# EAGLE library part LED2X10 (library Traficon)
PIN HEADER
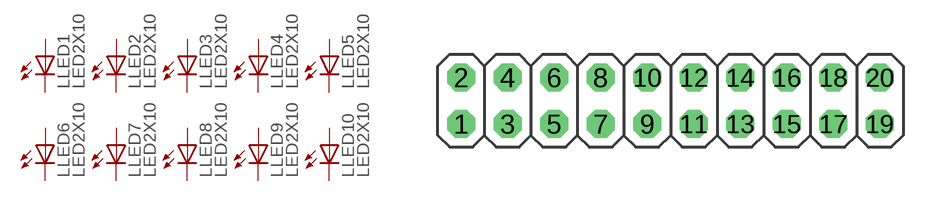
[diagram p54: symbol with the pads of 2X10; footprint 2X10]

Designator prefix L; gates LED1=LED-1 LED2=LED-1 LED3=LED-1 LED4=LED-1 LED5=LED-1 LED6=LED-1 LED7=LED-1 LED8=LED-1 LED9=LED-1 LED10=LED-1

## LED2X10  [2X10]
1  LED1:A  pas
2  LED2:A  pas
3  LED1:C  pas
4  LED2:C  pas
5  LED3:A  pas
6  LED4:A  pas
7  LED3:C  pas
8  LED4:C  pas
9  LED5:A  pas
10  LED6:A  pas
11  LED5:C  pas
12  LED6:C  pas
13  LED7:A  pas
14  LED8:A  pas
15  LED7:C  pas
16  LED8:C  pas
17  LED9:A  pas
18  LED10:A  pas
19  LED9:C  pas
20  LED10:C  pas

## Footprint 2X10 (pad centres in mm)
PIN HEADER
drill 1.016 octagon: 1 0,-2.54; 2 0,0; 3 2.54,-2.54; 4 2.54,0; 5 5.08,-2.54; 6 5.08,0; 7 7.62,-2.54; 8 7.62,0; 9 10.16,-2.54; 10 10.16,0; 11 12.7,-2.54; 12 12.7,0; 13 15.24,-2.54; 14 15.24,0; 15 17.78,-2.54; 16 17.78,0; 17 20.32,-2.54; 18 20.32,0; 19 22.86,-2.54; 20 22.86,0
